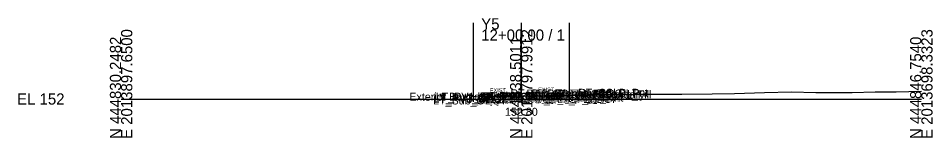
# Model space of a CAD drawing. Extents: x -26 to 203, y -10 to 4517.
# Drawn here: x -25.7 to 202.8, y 3990.3 to 4020.2 of the extents above; entities that cross this region are included whole.
import ezdxf

# ---------------------------------------------------------------- set-up
doc = ezdxf.new("R2010")
doc.units = 0
for name, color, linetype in [('Default', 7, 'Continuous'), ('Exist Cross Section Cell', 7, 'Continuous'), ('Exist XS Center Line Elevation Label', 7, 'Continuous'), ('Exist XS Ground Line', 7, 'Continuous'), ('Prop XS SE Text', 7, 'Continuous'), ('Scratch_Level_0', 7, 'Continuous'), ('Scratch_Level_1', 7, 'Continuous')]:
    doc.layers.add(name, color=color, linetype=linetype)

msp = doc.modelspace()

# ---------------------------------------------------------------- linework, layer by layer
at = {"layer": 'Exist Cross Section Cell'}
for p, q in [((100, 4000), (100, 4017.4)), ((0, 4000), (100, 4000)), ((100, 4000), (200, 4000))]:
    msp.add_line(p, q, dxfattribs=at)
at = {"layer": 'Exist XS Ground Line'}
msp.add_lwpolyline([(87.47, 4000.68), (87.9, 4000.69), (89.6, 4000.55), (92.5, 4000.63), (100, 4000.8), (101.12, 4000.82), (105.84, 4000.86), (112.07, 4000.89), (113.42, 4000.94), (113.94, 4000.99), (114.42, 4000.98), (117.39, 4001), (120.39, 4001.1), (127.89, 4001.17), (136.17, 4001.2), (138.79, 4001.24), (140.12, 4001.25), (147.74, 4001.27), (153.33, 4001.37), (160.84, 4001.63), (167.56, 4001.82), (173.62, 4001.6), (182.71, 4001.66), (188.48, 4001.83), (193.69, 4001.83), (200, 4001.95)], dxfattribs=at)
at = {"layer": 'Scratch_Level_1'}
for p, q in [((88, 4019.05), (88, 3999.31)), ((100, 4019.05), (100, 3999.31)), ((112, 4019.05), (112, 3999.31)), ((100, 4000.8), (89.6, 4000.55)), ((100, 4000.8), (105.84, 4000.86)), ((100, 4000.8), (112.26, 4000.8))]:
    msp.add_line(p, q, dxfattribs=at)

# ---------------------------------------------------------------- texts
at = {"layer": 'Default'}
msp.add_text('-', height=0.0001, dxfattribs=at).set_placement((0, 4000))
at = {"layer": 'Exist Cross Section Cell'}
for s, p in [('Y5', (90, 4017.4)), ('12+00.00 / 1', (90, 4014.6)), ('EL 152', (-26, 3998.6))]:
    msp.add_text(s, height=2.8, dxfattribs=at).set_placement(p)
for s, p in [('N 444830.2482', (0, 3990)), ('E 2013897.6500', (2.8, 3990)), ('N 444838.5011', (100, 3990)), ('E 2013797.9912', (102.8, 3990)), ('N 444846.7540', (200, 3990)), ('E 2013698.3323', (202.8, 3990))]:
    msp.add_text(s, height=2.8, rotation=90, dxfattribs=at).set_placement(p)
at = {"layer": 'Exist XS Center Line Elevation Label'}
msp.add_text('152.80', height=2, dxfattribs=at).set_placement((95.95, 3995.8))
at = {"layer": 'Prop XS SE Text'}
for rotation, p in [(1.1458, (92.16, 4001.64)), (0.5729, (104.25, 4001.84))]:
    msp.add_text('EXIST.', height=1, rotation=rotation, dxfattribs=at).set_placement(p)
at = {"layer": 'Scratch_Level_0'}
for s, p in [('Exterior Boundary', (72.04, 3999.56)), ('RT_PV1_OEEOP', (89.83, 3999.68)), ('LT_PV1_OEEOP', (89.87, 3999.68)), ('RT_PV1_IEEOP', (90.47, 3999.68)), ('LT_PV1_IEEOP', (90.52, 3999.68)), ('PV1_PGL', (94.47, 3999.8)), ('RT_Sub_Trench_Out_DLT', (97.28, 4000.41)), ('RT_CG_Top_Face', (101.28, 4000.36)), ('RT_PV2_OEOT', (102.19, 3999.67)), ('RT_CG_Top_Gut', (102.25, 3999.86)), ('RT_PV1_OEOT', (102.76, 3999.92)), ('RT_CG_Top_BOC', (102.8, 4000.36)), ('Exterior Boundary', (109.43, 4000.15)), ('RT_CSLP_Pnt', (114.19, 4000.55)), ('RT_Slope_Fill', (115.76, 4000.15)), ('LT_Sub_OEOT', (77.98, 3998.64)), ('LT_PV2_OEOT', (78.07, 3999.31)), ('LT_PV3_OEOT', (78.07, 3998.98)), ('LT_PV1_OEOT', (78.64, 3999.56)), ('RT_Sub_OEEOP', (89.17, 3998.88)), ('LT_Sub_OEEOP', (89.21, 3998.88)), ('RT_PV2_OEEOP', (89.26, 3999.55)), ('RT_PV3_OEEOP', (89.26, 3999.22)), ('LT_PV2_OEEOP', (89.31, 3999.55)), ('LT_PV3_OEEOP', (89.31, 3999.22)), ('RT_PV2_IEEOP', (89.91, 3999.55)), ('LT_PV2_IEEOP', (89.95, 3999.55)), ('PV2_PGL', (93.91, 3999.55)), ('RT_CG1_Shelf_Out', (101.57, 3999.37)), ('RT_CG_Bot_IE', (101.93, 3999.34)), ('RT_Sub_OEOT', (102.1, 3999.01)), ('RT_PV3_OEOT', (102.19, 3999.34)), ('RT_CG_Bot_BOC', (102.83, 3999.36)), ('RT_Sub_OEOP', (105.46, 3999.04))]:
    msp.add_text(s, height=2, dxfattribs=at).set_placement(p)

doc.saveas('drawing.dxf')
